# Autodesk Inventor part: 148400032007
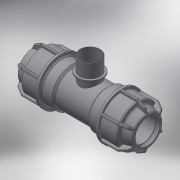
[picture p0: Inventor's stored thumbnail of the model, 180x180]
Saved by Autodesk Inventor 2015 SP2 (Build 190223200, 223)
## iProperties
Created: 2017-08
Part Number: 148400032007
Material: Generic
Description: PLASSON L.14 TEE MALE ADAPTOR (SILVER) 32-3/4"-32
Document SubType Name: Modeling
Designer: KIM
Density: 1 g/cm^3
Appearance: Default
Author: KIM
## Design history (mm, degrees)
derived "148400.ipt"
feature "Solid1::148400.ipt"
feature "Solid2::148400.ipt"
tag "TaggingFeature1"
body "Solid1"
body "Solid2"
other parameters: "d1" = 32, "d2" = 56, "d4" = 15 deg, "d5" = 36.96, "d6" = 12.1968, "d10" = 61, "d16" = 32.64, "d17" = 2.8, "d22" = 51.2, "d24" = 2.8, "d25" = 54.9, "d26" = 45.75, "d27" = 2.8, "d28" = 135 deg, "d29" = 1.68, "d31" = 1.6, "d46" = 150 deg, "d49" = 3.05, "d50" = 0, "d58" = 0.96, "d61" = 360 deg, "d63" = 28.8, "d64" = 75, "d80" = 46.08, "d81" = 2.56, "d84" = 2.8, "d94" = 49, "d96" = 26.441, "d108" = 0.96, "d111" = 0, "d113" = 25.6, "d114" = 31.7292, "d115" = 18, "d116" = 1.8, "d117" = 26.441, "d_" = 32, "R_" = 26.441, "E_" = 61, "l_" = 56, "l_2" = 18, "A_" = 49
